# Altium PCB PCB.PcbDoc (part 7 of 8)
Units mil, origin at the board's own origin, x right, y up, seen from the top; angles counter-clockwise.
Board outline 11229.24 x 7764.43 mil, 14 copper layers (Top Layer, GND1, Signal 1, GND2, Signal 2, GND3, Singal 3, Power 1, GND4, Power 2, GND5, Power 3, GND6, Bottom Layer), stack 91.892 mil thick; 877 components, 305 nets, 2660 pads, 2851 vias.
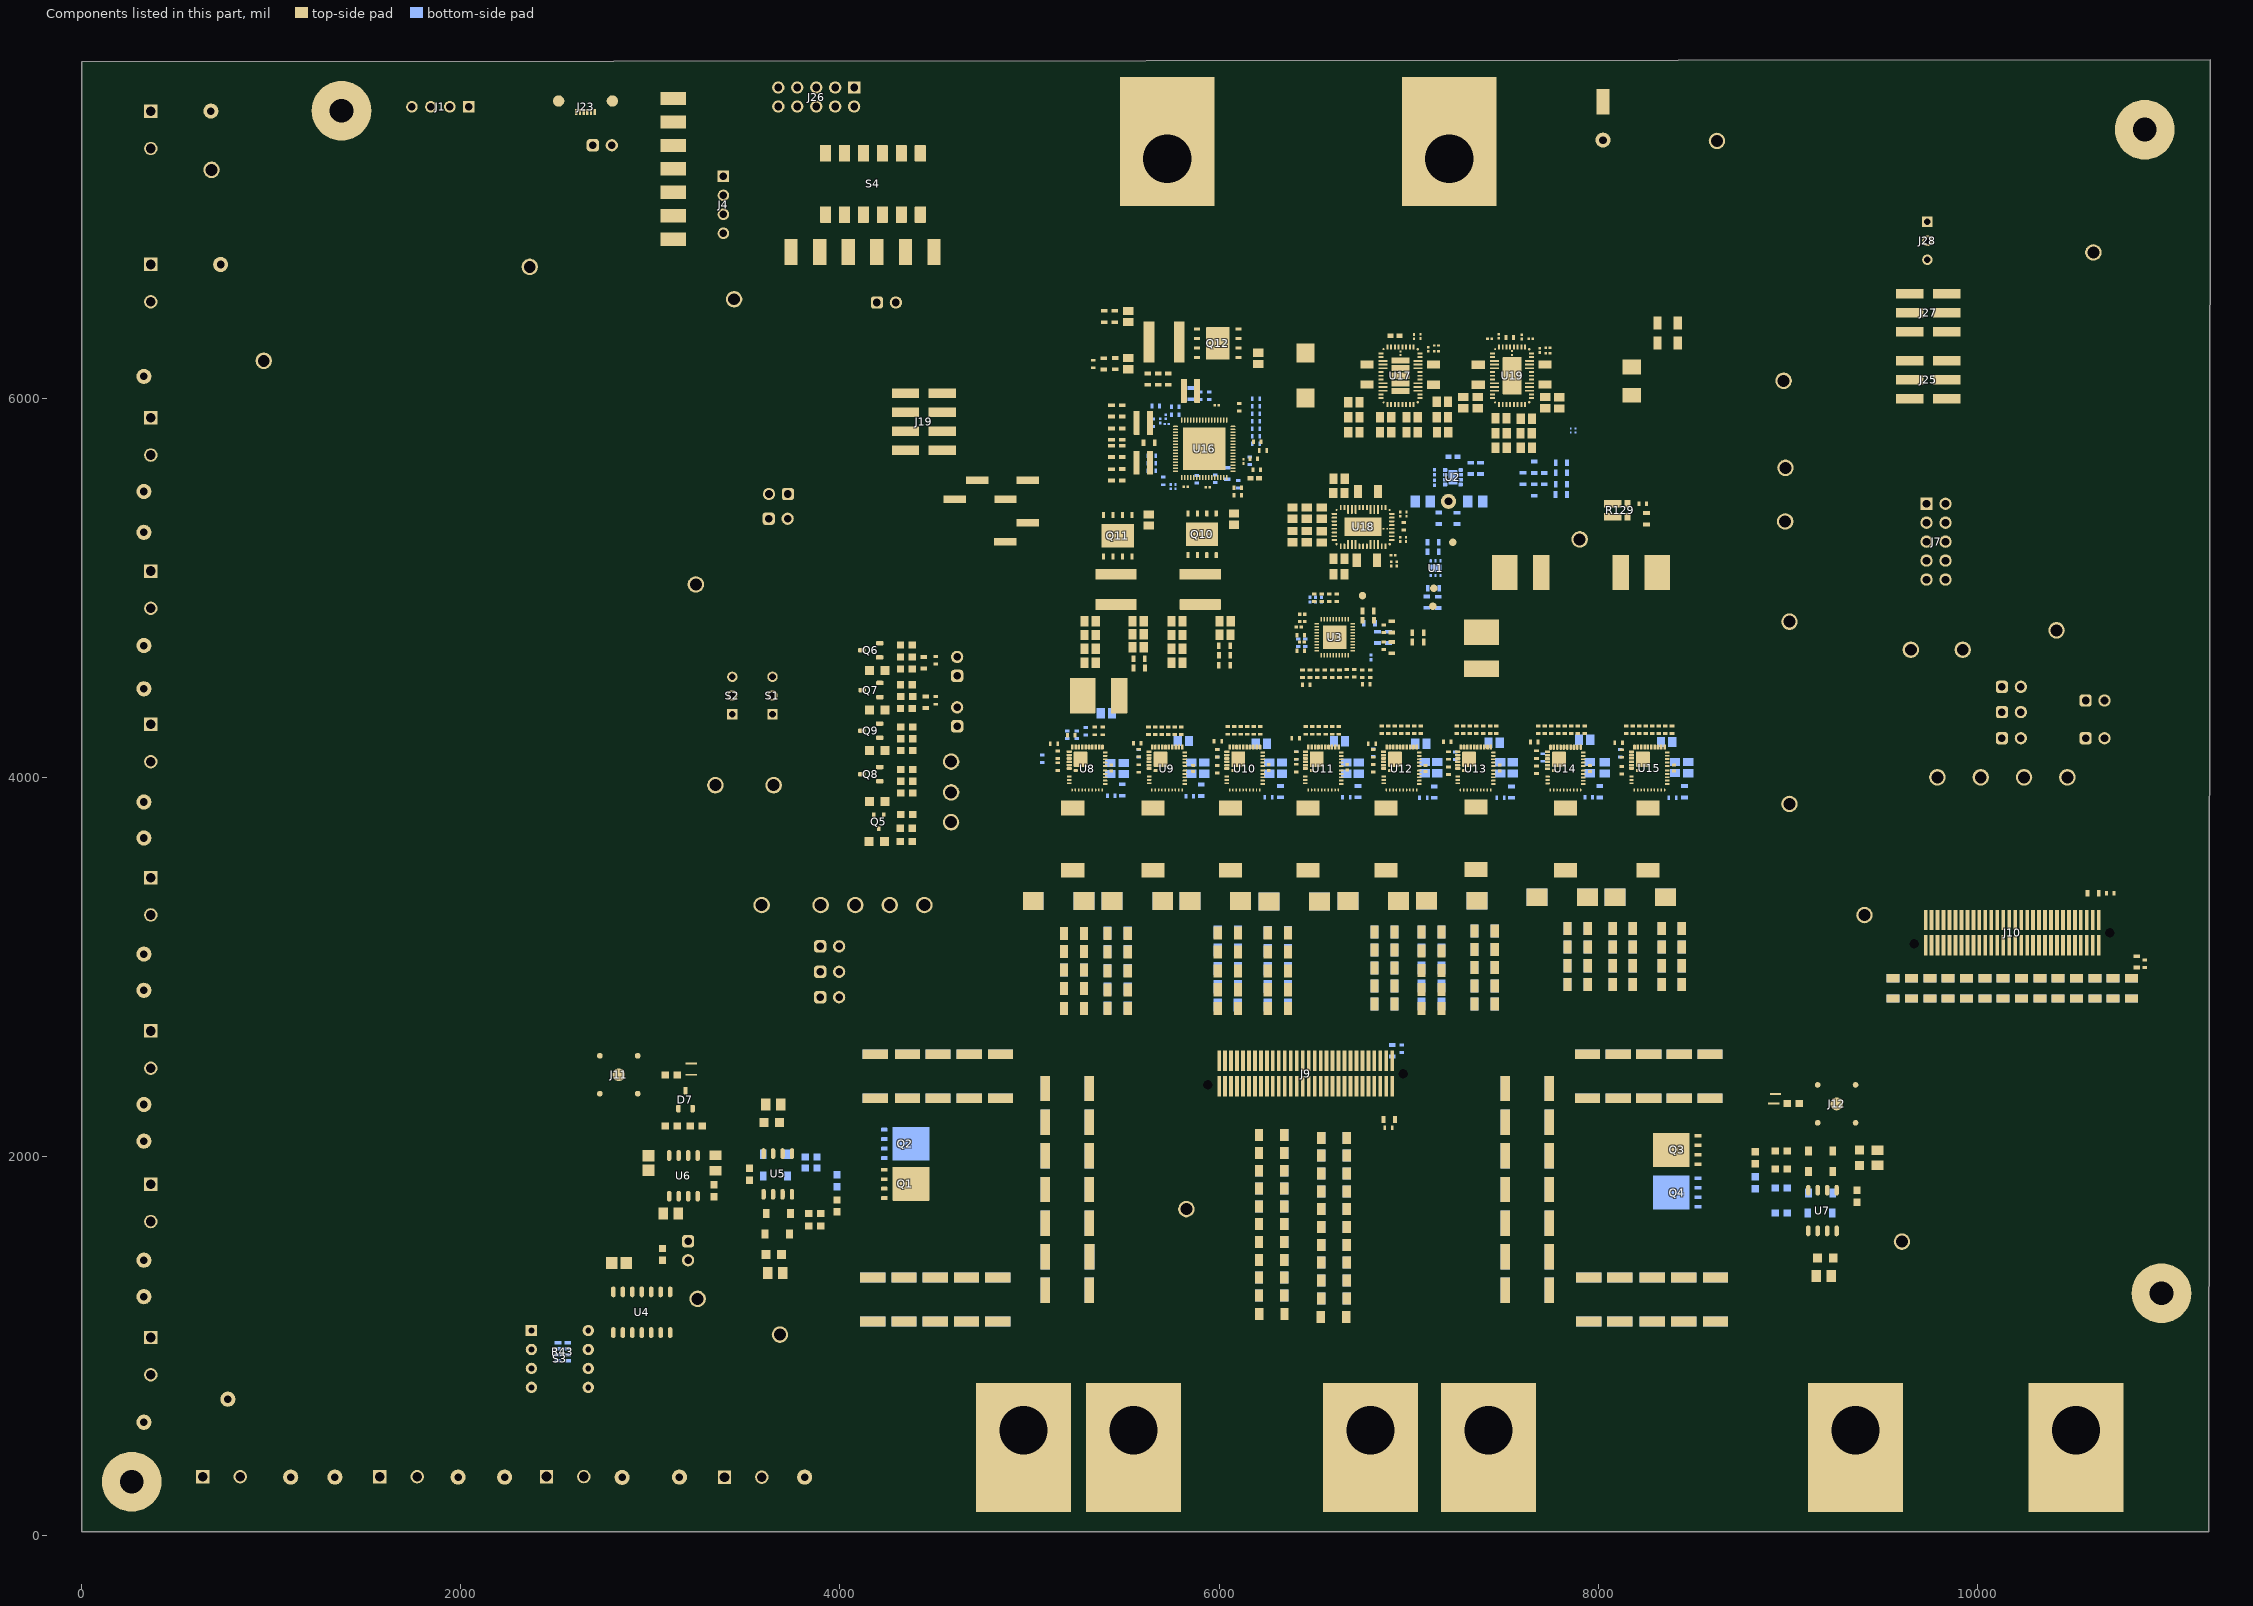
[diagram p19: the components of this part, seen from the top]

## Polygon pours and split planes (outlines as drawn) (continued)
GND on Top Layer "TOP_LAYER_GND_P228" (solid, pour order 228): 49.1,7702 70,7722.9 11155.9,7722.9 11174.4,7704.4 11168.51,7698.51 11168.51,107.92 11132.03,71.43 11131.56,71.9 93.47,71.43 49.1,115.8
NetC235_1 on Top Layer "TOP_LAYER_NETC235_1_P211" (solid, remove dead copper, pour order 211): 6807.22,3936.74 6807.22,3801.39 6814.15,3794.45 7033.7,3794.45 7058.6,3819.35 7058.6,3938.74 7050.65,3946.69 6817.16,3946.69
NetC219_1 on Top Layer "TOP_LAYER_NETC219_1_P210" (solid, remove dead copper, pour order 210): 6394.99,3935.22 6394.99,3802.13 6402.68,3794.45 6623.01,3794.45 6645.49,3816.94 6645.49,3938.97 6637.77,3946.69 6406.47,3946.69
NetC187_1 on Top Layer "TOP_LAYER_NETC187_1_P208" (solid, remove dead copper, pour order 208): 5577.22,3936.08 5577.22,3802.01 5585.13,3794.1 5804.01,3794.1 5821.44,3811.53 5821.44,3938.97 5813.71,3946.69 5587.83,3946.69
VINC on Top Layer "TOP_LAYER_VINC_P076" (solid, pour order 76): 137 vertices, not listed, extent 5316.29,4051.51 8511.42,5404.79
VTT on Top Layer "TOP_LAYER_VTT_P116" (solid, pour order 116): 6018.5,5591 6022.4,5594.9 6042.2,5594.9 6046.3,5590.8 6098.4,5538.7 6098.4,5453.31 6093.62,5448.53 6057.06,5448.53 6053,5452.59 6053,5533.3 6018.5,5567.8
VREF on Top Layer "TOP_LAYER_VREF_P231" (solid, pour order 231): 6802.4,4896.08 6806.85,4900.53 6858.37,4900.53 6881.85,4877.05 6881.85,4855.45 6876.6,4850.2 6808.23,4850.2 6802.4,4856.03
GND on Top Layer "TOP_LAYER_GND_P156" (solid, pour order 156): 9508.5,3112.9 9556.24,3160.63 10604.64,3160.63 10624.44,3140.83 10624.44,3022.13 10631.84,3014.73 10900.73,3014.73 10905.44,3010.02 10905.44,2911.95 10895.12,2901.63 9514.94,2901.63 9508.5,2908.07
PVOUT_B on Top Layer "TOP_LAYER_PVOUT_B_P153" (solid, pour order 153): 11070.28,3595.42 7686.78,3595.42 7606.48,3515.12 7606.48,2836.58 7763.18,2679.88 9197.62,2679.88 9908.91,1968.59 9908.91,77.59 9915.77,70.73 11123.43,70.73 11164.79,112.09 11164.79,3500.91
NetC267_1 on Top Layer "TOP_LAYER_NETC267_1_P094" (solid, remove dead copper, pour order 94): 7732.9,3937.63 7732.9,3811.11 7750.4,3793.6 7905.58,3793.6 7922.65,3810.67 7922.65,3938.11 7914.93,3945.84 7741.11,3945.84
BUCK6_OUT on Top Layer "TOP_LAYER_BUCK6_OUT_P213" (solid, pour order 213): 5786.29,4946.7 6022.99,4946.7 6029.09,4940.6 6029.09,4573.26 6022.22,4566.38 5786.61,4566.38 5780.49,4572.5 5780.49,4940.9
BUCK1_OUT on Top Layer "TOP_LAYER_BUCK1_OUT_P120" (solid, pour order 120): 5328.7,4946.7 5565.4,4946.7 5571.5,4940.6 5571.5,4558.67 5565.43,4552.6 5332.82,4552.6 5322.9,4562.52 5322.9,4940.9
NetC251_1 on Top Layer "TOP_LAYER_NETC251_1_P212" (solid, remove dead copper, pour order 212): 7256.4,3940.65 7256.4,3799.9 7261.85,3794.45 7446.23,3794.45 7453.4,3801.62 7453.4,3939.82 7446.53,3946.69 7262.44,3946.69
NetC203_1 on Top Layer "TOP_LAYER_NETC203_1_P209" (solid, remove dead copper, pour order 209): 5986.75,3935.88 5986.75,3801.47 5993.76,3794.45 6214.09,3794.45 6231.16,3811.53 6231.16,3938.97 6223.44,3946.69 5997.55,3946.69
NetC283_1 on Top Layer "TOP_LAYER_NETC283_1_P095" (solid, remove dead copper, pour order 95): 8175.92,3938.34 8175.92,3811.82 8193.43,3794.31 8348.6,3794.31 8365.67,3811.38 8365.67,3938.83 8357.95,3946.55 8184.13,3946.55
NetC171_1 on Top Layer "TOP_LAYER_NETC171_1_P011" (solid, remove dead copper, pour order 11): 5153.42,3935.4 5153.42,3802.55 5161.52,3794.45 5381.25,3794.45 5398.33,3811.53 5398.33,3938.97 5390.6,3946.69 5164.71,3946.69
VOUT_3 on Top Layer "TOP_LAYER_VOUT_3_P105" (solid, pour order 105): 21 vertices, not listed, extent 7548.67,5699.5 7840.57,6027.8
VOUT_1 on Top Layer "TOP_LAYER_VOUT_1_P202" (solid, pour order 202): 21 vertices, not listed, extent 6346.07,5025.8 6669.57,5317.7
VOUT_2 on Top Layer "TOP_LAYER_VOUT_2_P201" (solid, pour order 201): 21 vertices, not listed, extent 6346.07,5323.77 6669.57,5615.67
GND on Top Layer "TOP_LAYER_GND_P158" (solid, pour order 158): 7849.66,3422.79 7857.36,3430.49 8158.51,3430.49 8165.25,3423.74 8165.25,3296.64 8113.02,3244.42 8113.02,2862.1 8093.71,2842.79 7915.43,2842.79 7899.1,2859.12 7899.1,3251.6 7849.66,3301.04
5V_MODULE on Top Layer "TOP_LAYER_5V_MODULE_P103" (solid, pour order 103): 17 vertices, not listed, extent 6710.6,5677.3 7176.9,6027.8
NetQ1_5 on Top Layer "TOP_LAYER_NETQ1_5_P141" (solid, pour order 141): 4048.5,2479.92 4060.03,2491.46 5154.22,2491.46 5168.6,2477.08 5168.6,1204.52 5159.63,1195.56 4060.52,1195.56 4048.5,1207.58
GND on Top Layer "TOP_LAYER_GND_P143" (solid, pour order 143): 5204.7,3408.7 5212.4,3416.4 5504.4,3416.4 5509.2,3411.6 5509.2,3254.3 5468.06,3213.16 5468.06,2685.66 5458.5,2676.1 5243.7,2676.1 5236.1,2683.7 5236.1,3210.9 5204.7,3242.3
GND on Top Layer "TOP_LAYER_GND_P147" (solid, pour order 147): 6852.22,3403.64 6859.92,3411.34 7161.06,3411.34 7167.8,3404.6 7167.8,3260.33 7115.58,3208.1 7115.58,2751.63 7096.98,2733.04 6895.38,2733.04 6883.62,2744.81 6883.62,3205.84 6852.22,3237.24
NetQ3_5 on Top Layer "TOP_LAYER_NETQ3_5_P154" (solid, pour order 154): 8775.87,1207.09 8764.34,1195.56 7670.15,1195.56 7655.77,1209.93 7655.77,2482.49 7664.74,2491.46 8763.85,2491.46 8775.87,2479.43
PVOUT_A on Top Layer "TOP_LAYER_PVOUT_A_P167" (solid, pour order 167): 4043.8,2584.6 5043.1,3583.9 7495.66,3583.9 7562.77,3516.79 7562.77,2853.33 7756.1,2660 8774.2,2660 8778.8,2655.4 8778.8,76.18 8774.52,71.9 4048.35,71.9 4043.8,76.45
VIN on Top Layer "TOP_LAYER_VIN_P192" (solid, pour order 192): 50 vertices, not listed, extent 6073.6,6116.89 8353.5,7724.76
NetL1_2 on Top Layer "TOP_LAYER_NETL1_2_P099" (solid, pour order 99): 7882.72,6036.98 7917.73,6071.99 8517.11,6071.99 8539.5,6049.6 8539.5,5499.6 8516.14,5476.24 8135.84,5476.24 8133.26,5473.66 8133.26,5424.96 8124.1,5415.8 7890.87,5415.8 7882.72,5423.95
VIN on Top Layer "TOP_LAYER_VIN_P195" (solid, pour order 195): 6790.9,5249.3 6795,5253.4 6845.1,5253.4 6847.8,5250.7 6847.8,5201 6872.4,5176.4 6872.4,5109.8 6898.7,5083.5 6898.7,5022.8 6893.1,5017.2 6796.7,5017.2 6790.9,5023
VIN on Top Layer "TOP_LAYER_VIN_P193" (solid, pour order 193): 6789.7,5390.6 6794.3,5386 6843.1,5386 6848.2,5391.1 6848.2,5437.8 6871.3,5460.9 6871.3,5527.8 6897.6,5554.1 6897.6,5621.64 6891.74,5627.5 6766.84,5627.5 6759.86,5620.52 6759.86,5554.38 6789.89,5524.35
AGND2 on Top Layer "TOP_LAYER_AGND2_P186" (solid, pour order 186): 6879.68,5384.06 6913.05,5417.43 7007.57,5417.43 7021.62,5403.38 7021.62,5161.91 6952.08,5092.37 6898.59,5092.37 6879.68,5111.28
BUCK1_OUT on Top Layer "TOP_LAYER_BUCK1_OUT_P133" (solid, pour order 133): 4245.1,5851.29 4256.91,5863.1 4425.8,5863.1 4439.4,5849.5 4439.4,5363.8 5086,4717.2 5086,4589.46 5062.93,4566.38 4778.26,4566.38 4761.4,4583.25 4761.4,4634.1 4245.1,5150.4
PVIN345_V5ANA on Top Layer "TOP_LAYER_PVIN345_V5ANA_P125" (solid, pour order 125): 4455.9,5680.2 4455.9,6063.4 4476.1,6083.6 4738,6083.6 4760.8,6060.8 4760.8,5678.2 4744.84,5662.24 4473.86,5662.24
GND on Top Layer "TOP_LAYER_GND_P164" (solid, pour order 164): 7419.06,3231.51 7424.57,3237.01 7553.06,3237.01 7597.8,3192.27 7597.8,2768.1 7588.7,2759 7426.42,2759 7419.06,2765.84
GND on Top Layer "TOP_LAYER_GND_P159" (solid, pour order 159): 8406,3246.1 8411.5,3251.6 8540,3251.6 8549.78,3241.82 8549.78,2854.18 8538.38,2842.79 8415.57,2842.79 8406,2851.69
GND on Top Layer "TOP_LAYER_GND_P150" (solid, pour order 150): 17 vertices, not listed, extent 5981.3,1081.7 6897,2402.4
GND on Top Layer "TOP_LAYER_GND_P145" (solid, pour order 145): 6031.04,3408.71 6038.73,3416.4 6330.73,3416.4 6335.53,3411.6 6335.53,3254.3 6294.39,3213.16 6294.39,2756.69 6275.8,2738.1 6074.2,2738.1 6062.43,2749.87 6062.43,3210.9 6031.04,3242.3
PVINLDOA2_A3 on Top Layer "TOP_LAYER_PVINLDOA2_A3_P139" (solid, pour order 139): 4926.77,5373.75 4945.12,5392.1 5131.9,5392.1 5143.2,5380.8 5143.2,5313.8 5133.9,5304.5 4937.22,5304.5 4926.77,5314.95
BUCK6_OUT on Top Layer "TOP_LAYER_BUCK6_OUT_P137" (solid, pour order 137): 4534,5491.85 4548.75,5506.6 4930.9,5506.6 4953.1,5484.4 4953.1,5416.22 4915.69,5378.81 4915.69,5309.02 4953.1,5271.62 4953.1,5079.7 4929.8,5056.4 4808.9,5056.4 4786.9,5078.4 4786.9,5117.18 4545.58,5358.5 4534,5370.08
5V_MODULE on Top Layer "TOP_LAYER_5V_MODULE_P135" (solid, pour order 135): 4133.6,6073 4155.7,6095.1 4425.5,6095.1 4439.4,6081.2 4439.4,5887.25 4429.05,5876.9 4157.2,5876.9 4134,5900.1
VIN on Top Layer "TOP_LAYER_VIN_P129" (solid, pour order 129): 5923.63,5428.65 5937.28,5442.3 6216.24,5442.3 6225.03,5433.51 6225.03,5297.61 6217.53,5290.11 6131.53,5290.11 6121.93,5299.71 6121.93,5351.21 6106.83,5366.31 5926.43,5366.31 5923.63,5369.11
VIN on Top Layer "TOP_LAYER_VIN_P128" (solid, pour order 128): 5478.8,5431.2 5487.8,5440.2 5774.6,5440.2 5780.2,5434.6 5780.2,5290 5772.7,5282.5 5686.7,5282.5 5677.1,5292.1 5677.1,5343.6 5662,5358.7 5481.6,5358.7 5478.8,5361.5
BUCK2_OUT on Top Layer "TOP_LAYER_BUCK2_OUT_P126" (solid, pour order 126): 5665.66,6424.38 5665.66,6187.68 5659.56,6181.58 5218.76,6181.58 5200.56,6199.78 5200.56,6411.68 5219.06,6430.18 5659.86,6430.18
NetL12_1 on Top Layer "TOP_LAYER_NETL12_1_P123" (solid, pour order 123): 5898.25,6324.22 5900.75,6321.72 5900.75,6204.62 5881.75,6185.62 5760.95,6185.62 5756.85,6189.72 5756.85,6405.92 5763.95,6413.02 5815.15,6413.02 5821.25,6406.92 5821.25,6369.42 5866.45,6324.22
NetL11_1 on Top Layer "TOP_LAYER_NETL11_1_P119" (solid, pour order 119): 5430.3,5179 5432.8,5181.5 5549.9,5181.5 5568.9,5162.5 5568.9,5041.7 5564.8,5037.6 5348.6,5037.6 5341.5,5044.7 5341.5,5095.9 5347.6,5102 5385.1,5102 5430.3,5147.2
PVINLDOA2_A3 on Top Layer "TOP_LAYER_PVINLDOA2_A3_P117" (solid, pour order 117): 6058.5,5633.7 6060.8,5636 6087.8,5636 6121.5,5602.3 6178.84,5602.3 6182.47,5598.67 6182.47,5561.91 6177.46,5556.9 6126.3,5556.9 6105.6,5577.6 6105.6,5599.5 6079.6,5625.5 6060.8,5625.5 6058.5,5627.8
BUCK3_OUT on Top Layer "TOP_LAYER_BUCK3_OUT_P115" (solid, pour order 115): 5831.97,6101.13 5829.3,6103.8 5569.3,6103.8 5565.3,6099.8 5565.3,5974.6 5568.6,5971.3 5829.9,5971.3 5831.97,5973.37
BUCK4_OUT on Top Layer "TOP_LAYER_BUCK4_OUT_P114" (solid, pour order 114): 5578.34,5725.96 5582.4,5721.9 5582.4,5597 5578.5,5593.1 5316.3,5593.1 5310.7,5598.7 5310.7,5720.5 5316.16,5725.96
BUCK5_OUT on Top Layer "TOP_LAYER_BUCK5_OUT_P113" (solid, pour order 113): 5578.34,5936.16 5582.4,5932.1 5582.4,5807.2 5578.5,5803.3 5316.3,5803.3 5310.7,5808.9 5310.7,5930.7 5316.16,5936.16
LX4 on Top Layer "TOP_LAYER_LX4_P112" (solid, pour order 112): 5784.4,5721.99 5781.9,5719.49 5658.4,5719.49 5653.2,5714.29 5653.2,5595.89 5650.9,5593.59 5621.4,5593.59 5618.8,5596.19 5619.1,5596.49 5619.1,5721.19 5627.2,5729.29 5782.2,5729.29 5784.4,5727.09
PVIN345_V5ANA on Top Layer "TOP_LAYER_PVIN345_V5ANA_P110" (solid, pour order 110): 17 vertices, not listed, extent 5647,5735.6 5786.5,5793.2
LX5 on Top Layer "TOP_LAYER_LX5_P111" (solid, pour order 111): 5784.4,5805.9 5781.9,5808.4 5658.4,5808.4 5653.2,5813.6 5653.2,5932 5650.9,5934.3 5621.4,5934.3 5618.8,5931.7 5619.1,5931.4 5619.1,5806.7 5627.2,5798.6 5782.2,5798.6 5784.4,5800.8
LX3 on Top Layer "TOP_LAYER_LX3_P109" (solid, pour order 109): 5867,6100.2 5869.6,6102.8 5900.8,6102.8 5904.6,6099 5904.6,5873.2 5900.8,5869.4 5895.1,5869.4 5891.5,5873 5891.5,5940.9 5867,5965.4
AGND2_U19 on Top Layer "TOP_LAYER_AGND2_U19_P106" (solid, pour order 106): 20 vertices, not listed, extent 7450.7,6226.9 7763.6,6361.38
VOUT_4 on Top Layer "TOP_LAYER_VOUT_4_P104" (solid, pour order 104): 21 vertices, not listed, extent 7250.7,5704.3 7542.6,6027.8
GND on Top Layer "TOP_LAYER_GND_P102" (solid, pour order 102): 6880.1,5926.2 6885.6,5931.7 7010.4,5931.7 7015.7,5926.4 7015.7,5750.22 7012.08,5746.6 6883.6,5746.6 6880.1,5750.1
AGND1 on Top Layer "TOP_LAYER_AGND1_P100" (solid, pour order 100): 17 vertices, not listed, extent 6933.14,6232.4 7182.22,6403.19
VTT on Power 1 "POWER_1_VTT_P178" (solid, pour order 178): 31 vertices, not listed, extent 290.27,5448.31 6098.5,6780.1
GND on Power 1 "POWER_1_GND_P221" (solid, pour order 221): 49.1,7702 70,7722.9 11155.9,7722.9 11174.4,7704.4 11168.51,7698.51 11168.51,107.92 11132.03,71.43 11131.56,71.9 93.47,71.43 49.1,115.8
5V-AUX on Power 1 "POWER_1_5V-AUX_P098" (solid, pour order 98): 39 vertices, not listed, extent 2766.6,1488.77 7201.36,5319.65
BUCK6_OUT on Power 1 "POWER_1_BUCK6_OUT_P140" (solid, pour order 140): 6043,5546.3 6034,5555.3 6016.5,5555.3 6011.5,5550.3 6011.5,4800.27 5995.42,4784.19 5924,4784.19 5911.53,4771.73 5911.53,4699.27 5924.7,4686.1 5967.39,4686.1 6043,4761.8
LDOA1 on Power 1 "POWER_1_LDOA1_P175" (solid, pour order 175): 25 vertices, not listed, extent 1901.99,5939.24 5942.22,7574.3
LDOA3 on Power 1 "POWER_1_LDOA3_P174" (solid, pour order 174): 28 vertices, not listed, extent 2001.8,5577.6 6201.4,7575.1
5V-DRV on Power 1 "POWER_1_5V-DRV_P086" (solid, pour order 86): 17 vertices, not listed, extent 5050.5,4118.8 8315.68,5337.8
BUCK5_OUT on Power 1 "POWER_1_BUCK5_OUT_P181" (solid, pour order 181): 2968.6,5990.7 5397.6,5990.7 5408.4,5979.9 5408.4,5791 5396.4,5779 5004.2,5779 4838.2,5613 3968.5,5613 1151.4,2795.9 1151.4,104 1119.8,72.4 143.6,72.4 109.3,106.7 109.3,3131.4
VIN on Power 1 "POWER_1_VIN_P198" (solid, pour order 198): 6759.42,5622.76 6829.42,5692.76 7405.34,5692.76 7463.79,5634.31 7463.79,5555.29 7443.97,5535.47 7365.33,5535.47 7271.95,5628.85 6987.55,5628.85 6889.42,5530.73 6783.99,5530.73 6759.42,5555.3
VCCAUX on Power 1 "POWER_1_VCCAUX_P169" (solid, pour order 169): 23 vertices, not listed, extent 284.8,5869.05 5763.7,7567.9
BUCK4_OUT on Power 1 "POWER_1_BUCK4_OUT_P180" (solid, pour order 180): 4009,5571.6 4876.7,5571.6 5032.9,5727.8 5396,5727.8 5407.9,5715.9 5407.9,5480 4948.6,5020.7 4712.7,5020.7 2154,2462 2154,92.9 2133.9,72.8 1249.3,72.8 1221.5,100.6 1221.5,2784.1
PVIN345_V5ANA on Power 2 "POWER_2_PVIN345_V5ANA_P136" (solid, pour order 136): 19 vertices, not listed, extent 4612.1,5699.31 5899.49,6052.1
LDO3P3 on Power 2 "POWER_2_LDO3P3_P173" (solid, pour order 173): 24 vertices, not listed, extent 5650.75,5565.8 6142.8,5992.1
VREF on Power 2 "POWER_2_VREF_P085" (solid, pour order 85): 25 vertices, not listed, extent 5051.9,4162.59 8186.9,4878.2
5V_MODULE on Power 2 "POWER_2_5V_MODULE_P134" (solid, pour order 134): 29 vertices, not listed, extent 248.9,4930.8 7176.1,6134
GND on Power 2 "POWER_2_GND_P229" (solid, pour order 229): 49.1,7702 70,7722.9 11155.9,7722.9 11174.4,7704.4 11168.51,7698.51 11168.51,107.92 11132.03,71.43 11131.56,71.9 93.47,71.43 49.1,115.8
3.3V-Con on Power 2 "POWER_2_3.3V-CON_P084" (solid, pour order 84): 33 vertices, not listed, extent 2297.55,726.95 7183.9,4981.3
LDOA2 on Power 2 "POWER_2_LDOA2_P177" (solid, pour order 177): 25 vertices, not listed, extent 1793.36,5608.9 6193.6,7573.1
5V-AUX on Power 2 "POWER_2_5V-AUX_P096" (solid, pour order 96): 17 vertices, not listed, extent 7128.13,1823 9315.29,5410
PVINLDOA2_A3 on Power 2 "POWER_2_PVINLDOA2_A3_P138" (solid, pour order 138): 5085.4,5327.3 5085.4,5490.7 5146.74,5552.04 6074.04,5552.04 6125.76,5603.75 6156.49,5603.75 6166.65,5593.59 6166.65,5552.04 6105.31,5490.7 5168.4,5490.7 5143.9,5466.2 5143.9,5327.3 5128.9,5312.3 5100.4,5312.3
GND on Signal 1 "SIGNAL_1_GND_P216" (solid, pour order 216): 49.1,7702 70,7722.9 11155.9,7722.9 11174.4,7704.4 11168.51,7698.51 11168.51,107.92 11132.03,71.43 11131.56,71.9 93.47,71.43 49.1,115.8
SWA1 on Signal 1 "SIGNAL_1_SWA1_P176" (solid, pour order 176): 34 vertices, not listed, extent 1693.7,5560.42 5777.6,7573.9
GND on GND1 "GND1_GND_P215" (solid, pour order 215): 49.1,7702 70,7722.9 11155.9,7722.9 11174.4,7704.4 11168.51,7698.51 11168.51,107.92 11132.03,71.43 11131.56,71.9 93.47,71.43 49.1,115.8
VOUT_3 on Power 3 "POWER_3_VOUT_3_P191" (solid, pour order 191): 21 vertices, not listed, extent 93.9,4560.9 7874.5,6862.7
GND on Power 3 "POWER_3_GND_P225" (solid, pour order 225): 49.1,7702 70,7722.9 11155.9,7722.9 11174.4,7704.4 11168.51,7698.51 11168.51,107.92 11132.03,71.43 11131.56,71.9 93.47,71.43 49.1,115.8
PVIN345_V5ANA on Power 3 "POWER_3_PVIN345_V5ANA_P200" (solid, pour order 200): 6126.64,5747.65 6139.23,5735.07 6163.49,5735.07 6182.47,5754.05 6182.47,5904.84 6100.81,5986.5 5891.85,5986.5 5855.88,5950.53 5855.88,5924.64 5868.6,5911.92 5889.06,5911.92 5912.67,5935.53 6078.88,5935.53 6126.64,5887.76
LDO5V0 on Power 3 "POWER_3_LDO5V0_P199" (solid, pour order 199): 26 vertices, not listed, extent 5860.25,5513.8 6185.23,5931.5
VOUT_4 on Power 3 "POWER_3_VOUT_4_P190" (solid, pour order 190): 25 vertices, not listed, extent 109.8,3768.9 7449.8,6679.6
VOUT_1 on Power 3 "POWER_3_VOUT_1_P188" (solid, pour order 188): 17 vertices, not listed, extent 109.7,2171.6 6619.1,5221.73
VOUT_2 on Power 3 "POWER_3_VOUT_2_P189" (solid, pour order 189): 21 vertices, not listed, extent 109.7,2968 6557.97,5612.13
GND on GND2 "GND2_GND_P218" (solid, pour order 218): 49.1,7702 70,7722.9 11155.9,7722.9 11174.4,7704.4 11168.51,7698.51 11168.51,107.92 11132.03,71.43 11131.56,71.9 93.47,71.43 49.1,115.8
GND on Signal 2 "SIGNAL_2_GND_P217" (solid, pour order 217): 49.1,7702 70,7722.9 11155.9,7722.9 11174.4,7704.4 11168.51,7698.51 11168.51,107.92 11132.03,71.43 11131.56,71.9 93.47,71.43 49.1,115.8
GND on GND3 "GND3_GND_P219" (solid, pour order 219): 49.1,7702 70,7722.9 11155.9,7722.9 11174.4,7704.4 11168.51,7698.51 11168.51,107.92 11132.03,71.43 11131.56,71.9 93.47,71.43 49.1,115.8
GND on Singal 3 "SINGAL_3_GND_P220" (solid, pour order 220): 49.1,7702 70,7722.9 11155.9,7722.9 11174.4,7704.4 11168.51,7698.51 11168.51,107.92 11132.03,71.43 11131.56,71.9 93.47,71.43 49.1,115.8
GND on GND4 "GND4_GND_P222" (solid, pour order 222): 49.1,7702 70,7722.9 11155.9,7722.9 11174.4,7704.4 11168.51,7698.51 11168.51,107.92 11132.03,71.43 11131.56,71.9 93.47,71.43 49.1,115.8
GND on GND5 "GND5_GND_P224" (solid, pour order 224): 49.1,7702 70,7722.9 11155.9,7722.9 11174.4,7704.4 11168.51,7698.51 11168.51,107.92 11132.03,71.43 11131.56,71.9 93.47,71.43 49.1,115.8
GND on GND6 "GND6_GND_P226" (solid, pour order 226): 49.1,7702 70,7722.9 11155.9,7722.9 11174.4,7704.4 11168.51,7698.51 11168.51,107.92 11132.03,71.43 11131.56,71.9 93.47,71.43 49.1,115.8

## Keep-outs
Top Layer:
  region: 6085.2,5667.5 6100.6,5667.5 6103.9,5664.2 6136.2,5664.2 6138.3,5662.1 6138.3,5647.5 6136.5,5645.7 6101,5645.7 6092,5654.7 6085.2,5654.7
Bottom Layer:
  region: 3557.2,2042.9 3573.8,2059.5 3973.8,2059.5 4025.8,2007.5 4025.8,1812.6 4001.53,1788.33 3582.17,1788.33 3556.5,1814
Keep-Out Layer:
  text ".Layer_Name" at 577,-858.49 h60

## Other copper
Top Layer:
  pour cut-out: 8104.07,4135.24 8104.07,4157.16 8106.81,4159.9 8142.82,4159.9 8145.52,4157.2 8145.52,4142.59 8162.7,4125.41 8179.63,4125.41 8179.63,4107.5 8154.05,4107.5 8143.68,4117.88 8121.34,4117.88 8108.06,4131.16
  pour cut-out: 7654.67,4128.31 7654.67,4140.24 7664.61,4150.18 7687.36,4150.18 7695.05,4142.49 7695.05,4136.78 7706.74,4125.08 7729.15,4125.08 7729.15,4108.39 7696.88,4108.39 7680.18,4125.08 7657.84,4125.08 7657.58,4125.34
  pour cut-out: 7193.27,4120.69 7193.27,4149.44 7219.95,4149.44 7230.74,4138.65 7230.74,4132.13 7237.71,4125.16 7255.45,4125.16 7255.45,4108.58 7227.73,4108.58 7215.87,4120.43 7193.53,4120.43
  pour cut-out: 6793.62,4134.71 6793.62,4158.83 6795.28,4160.49 6831.29,4160.49 6833.99,4157.79 6833.99,4143.18 6851.17,4126 6868.1,4126 6868.1,4108.08 6842.52,4108.08 6819.12,4131.48 6796.78,4131.48 6796.52,4131.74
  pour cut-out: 6387.58,4123.78 6387.58,4147.89 6389.24,4149.55 6425.25,4149.55 6427.95,4146.85 6427.95,4132.24 6434.71,4125.48 6462.06,4125.48 6462.06,4107.43 6426.21,4107.43 6413.09,4120.55 6390.74,4120.55 6390.49,4120.81
  pour cut-out: 5970.48,4134.97 5970.48,4159.09 5972.14,4160.75 6008.15,4160.75 6010.85,4158.04 6010.85,4143.43 6028.03,4126.25 6044.96,4126.25 6044.96,4108.34 6019.38,4108.34 5995.98,4131.74 5973.64,4131.74 5973.38,4132
  pour cut-out: 5561.09,4134.04 5561.09,4158.16 5562.75,4159.82 5598.76,4159.82 5601.46,4157.12 5601.46,4142.51 5612.72,4131.25 5635.57,4131.25 5635.57,4113.48 5603.93,4113.48 5586.59,4130.81 5564.25,4130.81 5564,4131.07
  pour cut-out: 5128.2,4127.98 5128.2,4152.09 5129.86,4153.76 5165.87,4153.76 5168.57,4151.05 5168.57,4136.44 5179.83,4125.19 5202.68,4125.19 5202.68,4107.42 5171.03,4107.42 5153.7,4124.75 5131.36,4124.75 5131.1,4125.01
  pour cut-out: 9429.76,2347.4 9429.76,2208.6 9056.49,2208.6 9056.49,2347.4
  pour cut-out: 9056.43,2239.6 9056.43,2347.54 8893.82,2347.54 8893.82,2239.6
  pour cut-out: 3230.02,2392.3 3230.02,2500.24 3076.48,2500.24 3076.48,2392.3
  pour cut-out: 2670.24,2364.69 2670.24,2500.24 3076.48,2500.24 3076.48,2364.69
  text ".Layer_Name" at 577,-858.49 h60
Bottom Layer:
  text ".Layer_Name" at 577,-858.49 h60
Multi-Layer:
  pour cut-out: 10807.23,1214.25 ccw(c10969.96,1278.67) 11142.86,1251.55 ccw(c10969.96,1278.68)
  pour cut-out: 5557.35,6460.39 ccw(c5580.93,6460.39) 5580.93,6436.81 ccw(c5580.93,6460.39) 5604.51,6460.39 ccw(c5580.93,6460.39) 5580.93,6483.97 ccw(c5580.93,6460.39)
  pour cut-out: 8873.83,2304.29 ccw(c8873.83,2327.87) 8897.41,2327.87 ccw(c8873.83,2327.87) 8873.83,2351.45 ccw(c8873.83,2327.87) 8850.25,2327.87 ccw(c8873.83,2327.87)
  pour cut-out: 8184.39,2817.7 ccw(c8184.39,2841.28) 8207.97,2841.28 ccw(c8184.39,2841.28) 8184.39,2864.86 ccw(c8184.39,2841.28) 8160.81,2841.28 ccw(c8184.39,2841.28)
  pour cut-out: 8077.25,2819.21 ccw(c8077.25,2842.79) 8100.83,2842.79 ccw(c8077.25,2842.79) 8077.25,2866.37 ccw(c8077.25,2842.79) 8053.67,2842.79 ccw(c8077.25,2842.79)
  pour cut-out: 8873.83,2254.99 ccw(c8873.83,2278.57) 8897.41,2278.57 ccw(c8873.83,2278.57) 8873.83,2302.15 ccw(c8873.83,2278.57) 8850.25,2278.57 ccw(c8873.83,2278.57)
  pour cut-out: 6902.88,2746.04 ccw(c6926.45,2746.04) 6926.45,2722.46 ccw(c6926.45,2746.04) 6950.03,2746.04 ccw(c6926.45,2746.04) 6926.45,2769.62 ccw(c6926.45,2746.04)
  pour cut-out: 6796.58,2746.04 ccw(c6820.15,2746.04) 6820.15,2722.46 ccw(c6820.15,2746.04) 6843.73,2746.04 ccw(c6820.15,2746.04) 6820.15,2769.62 ccw(c6820.15,2746.04)
  pour cut-out: 3249.6,2489.38 ccw(c3273.18,2489.38) 3273.18,2465.8 ccw(c3273.18,2489.38) 3296.75,2489.38 ccw(c3273.18,2489.38) 3273.18,2512.96 ccw(c3273.18,2489.38)
  pour cut-out: 3248.3,2429.64 ccw(c3271.88,2429.64) 3271.88,2406.07 ccw(c3271.88,2429.64) 3295.45,2429.64 ccw(c3271.88,2429.64) 3271.88,2453.22 ccw(c3271.88,2429.64)

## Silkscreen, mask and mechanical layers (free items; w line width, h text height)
Top Overlay:
  lines w8: 7106.28,2522.7 7193.7,2522.7 7211.52,2540.52 7211.52,3217.6 7197.62,3231.51 7161.06,3231.51 ; 7108.1,2709.2 7210.6,2709.2 ; 7311.15,2709.2 7426.42,2709.2
  lines w10: 4293.12,5876.9 4262.08,5876.9 4229.3,5909.68 4229.3,6065.99 4242.11,6078.8 4274.3,6078.8 4300.76,6078.8 ; 4295.1,5676.1 4259.01,5676.1 4229.3,5705.81 4229.3,5832.43 4259.97,5863.1 4295.1,5863.1 ; 4960.8,5191.5 4950.12,5180.81 4950.7,3431.74 4950.7,2734.7 7209.2,2734.7 ; 4960.8,5616.3 4962.6,6494.6 8472.5,6494.6 ; 5548,-48 5566,-66 ; 6156.84,5648.7 6358.89,5648.7 6377.69,5667.5 6486.5,5667.5 ; 6225.03,5025.8 6551.87,5025.8 6565.07,5039 6565.07,5181.22 6573.18,5189.33 6581.51,5189.33 ; 6233.1,4906.27 6233.1,4991.09 6249,5006.98 6633.61,5006.98 6649.51,4991.09 6649.51,4966.58 ; 6233.1,5114.33 6324.06,5114.33 6331.3,5107.09 6331.3,5025.8 ; 6385.74,4906.31 6385.74,5006.98 ; 6468.21,4966.58 6468.21,5006.98 ; 7084.54,5560.9 7157.97,5560.9 7181.38,5584.31 7181.38,5705.32 7243.7,5767.64 7243.7,6017.45 7237.11,6024.04 7186.62,6024.04 ; 7310.08,2724.26 7793.29,2724.26 ; 7370.84,3234.21 7321.05,3234.21 7310.08,3223.24 7310.08,2543.72 7331.1,2522.7 7426.42,2522.7 ; 7796.95,2838.93 7911.6,2838.96 ; 7853.53,3248.85 7796.95,3248.85 7796.95,2744.73 7796.95,2711.1 7822.26,2685.8 7911.6,2685.8 ; 7911.6,2726.05 8075.82,2725.93 ; 8186.73,2724.26 8310.8,2724.26 ; 8414.03,2724.26 8479.19,2724.26 8479.19,2839.73 ; 31.4,39.45 3938.3,39.45 3938.3,591.3 3917.5,612.1 889.8,612.1 889.8,2160.2 888.3,2161.7 31.4,2161.7 31.4,39.45 ; 32.2,2178.7 889.3,2178.7 889.3,3751.1 32.2,3751.1 32.2,2178.7 ; 32.2,3796.1 889.3,3796.1 889.3,5368.5 32.2,5368.5 32.2,3796.1 ; 3134.4,2732.69 4745.2,2732.69 4745.2,4828.1 3134.4,4828.1 3134.4,2732.69 ; 3518.81,2765.11 4411.57,2765.11 4411.57,3180.27 3518.81,3180.27 3518.81,2765.11 ; 3726.6,3203.37 4619.37,3203.37 4619.37,3583.9 3726.6,3583.9 3726.6,3203.37 ; 9355.5,3784.27 10119.5,3784.27 10119.5,4102 9355.5,4102 9355.5,3784.27 ; 9357.6,4116.8 10314.3,4116.8 10314.3,4552.9 9357.6,4552.9 9357.6,4116.8 ; 9465.2,4798.2 10096.2,4798.2 10096.2,5800.7 9465.2,5800.7 9465.2,4798.2 ; 10133.9,3784.27 10897.9,3784.27 10897.9,4102 10133.9,4102 10133.9,3784.27 ; 10473.6,4115.2 11132.7,4115.2 11132.7,4613.3 10473.6,4613.3 10473.6,4115.2
  text "VCCAUX" at 68.7,7584.4 h60 r270
  text "SCL" at 3240.8,7558.7 h60
  text "VIN" at 8118.3,7530.5 h60
  text "TPS650861 / Programmer" at 4314,7503.5 h60
  text "VCCAUX" at 784.9,7486.2 h60
  text "TPS650861 / Ribbon Programmer" at 2238.9,7475.9 h60 r270
  text "SWA1" at 1693.95,7435.06 h60 r270
  text "LDOA2" at 1807.55,7435.06 h60 r270
  text "LDOA1" at 1921.15,7435.06 h60 r270
  text "LDOA3" at 2034.75,7435.06 h60 r270
  text "SDA" at 3236.2,7422.38 h60
  text "IRQB" at 3255.2,7301.8 h60
  text "GND" at 8541.2,7191.6 h60
  text "GND" at 818.84,7174.45 h60
  text "GPO1" at 2792.23,7166.6 h60
  text "GPO1" at 3479.5,7148.6 h60
  text "GPO2" at 2772.24,7050.63 h60
  text "GPO2" at 3479.5,7042.63 h60
  text "GPO3" at 3479.5,6938.6 h60
  text "GPO3" at 2772.24,6927.7 h60
  text "EN" at 9510.93,6898.8 h60
  text "GPO4" at 3479.5,6841.17 h60
  text "GPO4" at 2772.24,6802.8 h60
  text "U17_EN" at 9281,6796.9 h60
  text "OFF" at 9450.94,6699.1 h60
  text "VTT" at 68.7,6678.8 h60 r270
  text "VTT" at 852.8,6672.1 h60
  text "CTL1" at 3710.2,6635.5 h60 r270
  text "CTL2" at 3861.12,6635.5 h60 r270
  text "CTL3" at 4012.04,6635.48 h60 r270
  text "CTL5" at 4370.4,6635.48 h60 r270
  text "CTL6" at 4476,6635.48 h60 r270
  text "GND" at 10511.95,6575.78 h60
  text "EN" at 9384.31,6529.6 h60
  text "EN" at 10009.4,6527.1 h60
  text "GND" at 2275.64,6504.65 h60
  text "U19_EN1" at 9114.4,6434.45 h60
  text "U19_EN2" at 10009.4,6422.25 h60
  text "CTL4" at 4132.8,6369.2 h60
  text "GND" at 3359.34,6351.95 h60
  text "OFF" at 9324.33,6329.9 h60
  text "OFF" at 10009.4,6327.4 h60
  text "EN" at 9384.31,6175.9 h60
  text "EN" at 10008.3,6173.4 h60
  text "GND" at 1112.3,6160.4 h60
  text "U18_EN1" at 9114.4,6071.5 h60
  text "U18_EN2" at 10008.6,6071.5 h60
  text "5V_MODULE" at 68.7,6060 h60 r270
  text "OFF" at 9324.33,5976.2 h60
  text "OFF" at 10008.3,5973.7 h60
  text "5V_MODULE" at 3686.5,5967.4 h60
  text "GND" at 8886.1,5920.6 h60
  text "BUCK1_OUT" at 3696.5,5743.69 h60
  text "TPS53688 PMBUS" at 9504.19,5718.98 h72.83
  text "PVIN345_ / V5ANA" at 4854.2,5688.9 h60 r90
  text "PVINSWB1_B2" at 4606.25,5632.82 h40
  text "PVINSWA1" at 5011.2,5613.93 h40
  text "VOUT_B SENSE" at 3347.9,5590.5 h60
  text "BUCK6_OUT" at 4290.6,5451.3 h40
  text "5V_INT" at 7299.21,5450.97 h60
  text "TPS53688" at 2970.5,5405.6 h60
  text "BUCK6_OUT" at 4634.99,5365.6 h40
  text "VINC" at 7671.03,5350.2 h60
  text "U19 Module Output" at 782.29,5318.5 h60 r270
  text "PVINLODA2_A3" at 5009.6,5275.96 h40
  text "BUCK6_OUT" at 4565.8,5228.83 h40
  text "VOUT_A SENSE" at 3347.9,5220.3 h60
  text "5V-DRV" at 7124.1,5168.35 h60
  text "VOUT_3" at 68.7,5163.1 h60 r270
  text "TPS53688 Current  / Sense Resistor" at 9209.28,5093.65 h72.83 r90
  text "3V3-LDO" at 7052.54,5032.12 h60
  text "GND" at 2938.84,4982.75 h60
  text "VREF" at 6779.6,4957.8 h60
  text "3V3-CON" at 7167.38,4890.31 h60
  text "GND" at 10338.5,4861.6 h60
  text "TPS53688 EN and Indication LEDs" at 3334.03,4858.78 h90
  text "ON" at 3491.4,4705.4 h60
  text "TSENB" at 9373.7,4655.87 h60
  text "TSENA" at 10019.3,4655.87 h60
  text "GND" at 8910.18,4636.15 h60
  text "1" at 3973.19,4566.2 h60
  text "BCSP" at 10507.9,4517.6 h60
  text "ACSP" at 9389.57,4459.05 h60
  text "EN_VOUT_B" at 4720.33,4455.9 h50 r90
  text "IOUT4" at 9697.3,4450.8 h60
  text "BIOUT2" at 10764.82,4380.05 h60
  text "VOUT_4" at 68.7,4340 h60 r270
  text "2" at 3953.2,4328.2 h60
  text "IOUT5" at 9697.3,4316.3 h60
  text "EN_VOUT_B" at 3294,4184.1 h60 r90
  text "EN_VOUT_A" at 3829.9,4184.1 h60 r90
  text "BIOUT1" at 10764.82,4174.55 h60
  text "IOUT6" at 9697.3,4173.5 h60
  text "EN_VOUT_A" at 4720.33,4170.34 h50 r90
  text "3" at 3953.2,4127.1 h60
  text "OFF" at 3464.8,4100.5 h60
  text "APWM" at 9383.5,4002.3 h60
  text "BPWM" at 10621.9,3976.9 h60
  text "4" at 3953.2,3851.7 h60
  text "5" at 9763.87,3819.6 h60
  text "6" at 9996.95,3819.6 h60
  text "2" at 10226.15,3819.6 h60
  text "1" at 10471.2,3819.6 h60
  text "EN_VOUT_B" at 3179.6,3818.36 h60
  text "EN_VOUT_A" at 3553.7,3818.36 h60
  text "U18 Module Output" at 787.09,3715.6 h60 r270
  text "GND" at 8929.18,3685.35 h60
  text "Phase A and B PWM and Iout Test Points" at 9408.06,3685.35 h72.83
  text "5" at 3953.2,3665.1 h60
  text "VOUT_2" at 67.4,3539.7 h60 r270
  text "APWM" at 3744.5,3503.1 h90
  text "1. EN_VOUT_B / 2. EN_VOUT_A / 3. VOUT_A_RDY / 4. VOUT_B_RDY / 5. VR_FAULT#" at 3255.8,3458.2 h60
  text "1" at 4442.18,3426.4 h60
  text "2" at 4245.51,3422.55 h60
  text "4" at 3865.7,3419 h60
  text "3" at 4068.4,3419 h60
  text "GND" at 3288.4,3283.1 h60
  text "PVOUT_B" at 8985.12,3095.24 h60
  text "IOUT3" at 4097.7,3078.3 h60
  text "ACSP" at 3545.2,3074.1 h60
  text "IOUT2" at 4097.7,2942.2 h60
  text "IOUT1" at 4097.7,2807.6 h60
  text "VOUT_1" at 69.9,2719.9 h60 r270
  text "C240_Out" at 2649.2,2678.7 h60
  text "C147_Out" at 9010.67,2511.45 h60
  text "TPS650861 Output" at 771.09,2104.8 h60 r270
  text "BUCK2_OUT" at 69.9,2007.1 h60 r270
  text "PVOUT_A" at 5584.3,1539.5 h60
  text "GND" at 9512.77,1369.87 h60
  text "BUCK3_OUT" at 68.5,1196.3 h60 r270
  text "PVOUT_B" at 10318.2,972.6 h60
  text "PVOUT_A" at 6930.1,965.5 h60
  text "GND" at 3598.4,883.2 h60
  text "BUCK5_OUT" at 532.2,57.78 h50
  text "BUCK4_OUT" at 1455.85,57.78 h50
  text "BUCK6_OUT" at 2331.67,57.78 h50
  text "BUCK1_OUT" at 3284.84,57.78 h50
  text ".Layer_Name" at 577,-858.49 h60
Bottom Overlay:
  text ".Layer_Name" at 577,-858.49 h60
Top Paste:
  text ".Layer_Name" at 577,-858.49 h60
Bottom Paste:
  text ".Layer_Name" at 577,-858.49 h60
Top Solder:
  text ".Layer_Name" at 577,-858.49 h60
  text ".Layer_Name" at 577,-858.49 h60
Bottom Solder:
  text ".Layer_Name" at 577,-858.49 h60
Drill Guide:
  text ".Layer_Name" at 577,-858.49 h60
M1 Board Outline:
  lines w10: 0,21 11220.99,21 11229.68,7785.03 0,7775.19 0,21
  text ".Layer_Name" at 577,-858.49 h60
M2 Board Dimensions:
  rectangle: 0,-275 125,-150
  rectangle: 125,-400 500,-275
  lines w7: 0,-275 1000,-275 ; 125,-400 125,-150 ; 250,-400 250,-150 ; 500,-400 500,-150 ; 750,-400 750,-150 ; 0,-400 1000,-400 1000,-150 0,-150 0,-400
  text ".Layer_Name" at 577,-858.49 h60
M3 3D STEP Top:
  text ".Layer_Name" at 577,-858.49 h60
M4 3D STEP Bottom:
  text ".Layer_Name" at 577,-858.49 h60
M5 Assembly Top:
  lines w10: -292,-930.17 6308,-930.17 ; -292,-726.83 6310,-726.83 ; -292,-523.5 -292,-1133.5 3713,-1133.5 6310,-1133.5 6310,-523.5 -291.5,-523.5 -291.5,-1133.5 1284,-1133.5 ; 2173,-1133.5 2173,-523.5 ; 3440,-726.83 3440,-523.5 ; 4280,-726.83 4280,-523.5 ; 4902,-1140 4902,-937.17
  text "COMPONENTS MARKED 'DNP' SHOULD NOT BE POPULATED." at 1153.5,-318.5 h60
  text "ASSEMBLY VARIANT:" at 1153,-434 h60
  text ".VariantName" at 2189,-434 h60
  text "PCB VIEWED FROM TOP SIDE" at -228.5,-655.67 h60
  text "BOARD #:" at 2248,-655.67 h60
  text ".PRJ_Number" at 2793.5,-655.67 h60
  text "REV:" at 3638,-655.67 h60
  text ".PCB_Rev" at 3929.5,-655.67 h60
  text "SVN REV:" at 4476,-655.67 h60
  text ".VersionControl_RevNumber" at 4982,-655.67 h60
  text "TID #:" at 2248,-859 h60
  text ".TID" at 2793.5,-859 h60
  text "PLOT NAME =" at -228.5,-1064.34 h60
  text ".plot_File_Name" at 577,-1064.34 h60
  text "GENERATED    :" at 2250,-1064.34 h60
  text ".Print_Date" at 3119.5,-1064.34 h60
  text ".Print_Time" at 3848.5,-1064.34 h60
  text "TEXAS INSTRUMENTS" at 5113,-1064.34 h60
M6 Assembly Bottom:
  lines w10: -292.5,-727.33 6309.5,-727.33 ; -290.5,-930.67 6309.5,-930.67 ; 1115.5,-1140.5 1115.5,-937.67 ; 1737.5,-727.33 1737.5,-524 ; 2577.5,-727.33 2577.5,-524 ; 3844.5,-1134 3844.5,-524 ; 4733.5,-1134 6309,-1134 6309,-524 -292.5,-524 -292.5,-1134 2304.5,-1134 6309.5,-1134 6309.5,-524
  text "COMPONENTS MARKED 'DNP' SHOULD NOT BE POPULATED." at 6102,-318 h60
  text ".VariantName" at 5058,-434 h60
  text "ASSEMBLY VARIANT:" at 6097,-434 h60
  text ".VersionControl_RevNumber" at 1035.5,-656.17 h60
  text "SVN REV:" at 1541.5,-656.17 h60
  text ".PCB_Rev" at 2088,-656.17 h60
  text "REV:" at 2379.5,-656.17 h60
  text ".PRJ_Number" at 3224,-656.17 h60
  text "BOARD #:" at 3769.5,-656.17 h60
  text "PCB VIEWED FROM BOTTOM SIDE" at 6246,-656.17 h60
  text ".TID" at 3224,-859.5 h60
  text "TID #:" at 3769.5,-859.5 h60
  text "TEXAS INSTRUMENTS" at 904.5,-1064.84 h60
  text ".Print_Time" at 2169,-1064.84 h60
  text ".Print_Date" at 2898,-1064.84 h60
  text "GENERATED    :" at 3767.5,-1064.84 h60
  text ".plot_File_Name" at 5440.5,-1064.84 h60
  text "PLOT NAME =" at 6246,-1064.84 h60
M9 Title Sheet:
  drawing of 57 lines, arcs and shapes, not listed
  text "1" at 739.84,8036.5 h70
  text "2" at 3235.5,8036.5 h70
  text "3" at 5724.84,8036.5 h70
  text "4" at 8231.51,8036.5 h70
  text "5" at 10730.5,8036.5 h70
  text "6" at 13235.5,8036.5 h70
  text "A" at -416.5,6893.5 h70
  text "A" at 14383.5,6893.5 h70
  text "B" at -416.5,4513.5 h70
  text "B" at 14383.5,4513.5 h70
  text "C" at -416.5,2138.5 h70
  text "C" at 14383.5,2138.5 h70
  text "PROJECT TITLE:" at 11343.5,277.5 h45
  text ".PRJ_Title" at 11393.5,144.17 h70
  text "DESIGNED FOR:" at 11343.5,-23.5 h45
  text ".PRJ_Customer" at 11393.5,-163.5 h70
  text "D" at -416.5,-231.5 h70
  text "D" at 14383.5,-231.5 h70
  text "FILE NAME:" at 11343.5,-323.5 h45
  text ".PCB_File_Name_No_Path" at 11393.5,-443.5 h70
  text "Texas Instruments (TI) and/or its licensors do not warrant the accuracy or completeness of this specification" at 6374,-605.34 h45
  text "ENGINEER:" at 11343.5,-613.5 h45
  text "LAYOUT BY:" at 12848.5,-613.5 h45
  text "or any information contained therein. TI and/or its licensors do not warrant that this design will meet" at 6329.01,-718 h45
  text ".PRJ_Engineer" at 11393.5,-768.49 h70
  text ".PCB_Layout" at 12899,-768.49 h70
  text "the specifications, will be suitable for your application or fit for any particular purpose, or will operate in" at 6329.01,-830.67 h45
  text ".Layer_Name" at 577,-858.49 h60
  text "ALTIUM DESIGNER VERSION:" at 12848.5,-923.5 h45
  text "an implementation. TI and/or its licensors do not warrant that the design is production worthy. You should" at 6329.01,-943.33 h45
  text "completely validate and test your design implementation to confirm the system functionality for your application." at 6374,-1056 h45
  text ".print_Scale" at 11393.5,-1056.83 h70
  text ".Application_BuildNumber" at 12899,-1056.83 h70
  text "1" at 739.84,-1263.5 h70
  text "2" at 3235.5,-1263.5 h70
  text "3" at 5724.84,-1263.5 h70
  text "4" at 8231.51,-1263.5 h70
  text "5" at 10730.5,-1263.5 h70
  text "6" at 13235.5,-1263.5 h70
M10 Fab Notes:
  drawing of 189 lines, arcs and shapes, not listed
  text "DESIGN INFORMATION" at 12382.02,6356.17 h60
  text "MIN. TRACK WIDTH:" at 11737.46,6224.05 h60
  text "8" at 12833.7,6224.05 h60
  text "MIL" at 12988.46,6224.05 h60
  text "MIN. CLEARANCE:" at 11737.46,6099.92 h60
  text "7.874" at 12667.32,6099.92 h60
  text "MIL" at 12988.46,6099.92 h60
  text "MIN. VIA PAD SIZE:" at 11737.46,5975.8 h60
  text "24" at 12803.71,5975.8 h60
  text "MIL" at 12988.46,5975.8 h60
  text "0.05mm (2MIL)" at 12432.46,5845.9 h60
  text "MINIMUM ANNULAR RING" at 11408.23,5837.67 h60
  text "EXTERNAL" at 13140.46,5837.67 h60
  text "PER" at 11608.23,5727.55 h60
  text "IPC-D-275 CLASS 2 LEVEL C" at 11828.23,5727.54 h60
  text "MIL, HOLES" at 13316.46,5627.07 h60
  text "+/-" at 12924,5618.48 h60
  text "+/-" at 13778,5618.48 h60
  text "REGISTRATION TOLERANCES:" at 11408.23,5617.42 h60
  text "METAL" at 12608,5617.42 h60
  text "5" at 13184.2,5617.42 h60
  text "3" at 14017.2,5617.42 h60
  text "MIL" at 14133.46,5617.42 h60
  text "HOLE SIZE TOLERANCE (UNLESS OTHERWISE SPECIFIED):" at 11408.23,5519.1 h60
  text "+/-" at 13778,5516.23 h60
  text "3" at 14017.2,5515.17 h60
  text "MIL" at 14133.46,5515.17 h60
  text "MATERIAL:" at 11333.46,5377.52 h60
  text "FR-4 High Tg" at 12319.9,5249 h60
  text "X" at 12175.46,5241.01 h60
  text "FR-408" at 11754.46,5236.49 h60
  text "OTHER" at 13242.46,5236.49 h60
  text "X" at 13241.12,5103.9 h60
  text "62 MIL (1.6mm) +/-10%" at 12074.56,5093.46 h60
  text "96 MIL (2.4mm) +/-10%" at 13667.36,5088.46 h60
  text "THICKNESS:" at 11408.23,5085.24 h60
  text "OTHER" at 13359.46,5085.24 h60
  text "TOLERANCE:" at 11408.23,4946.92 h60
  text "X" at 12256.46,4946.92 h60
  text "ANSI IPC-6012 TYPE 3 CLASS 2" at 12434.48,4946.92 h60
  text "OTHER +/-" at 12434.46,4802.73 h60
  text "BOW & TWIST:" at 11408.23,4657.54 h60
  text "X" at 12256.46,4657.54 h60
  text "ANSI IPC-6012 TYPE 3 CLASS 2" at 12434.48,4657.54 h60
  text "OTHER +/-" at 12434.46,4510.85 h60
  text "DRILLING:" at 11333.46,4380.23 h60
  text "NC_DRILL FILES" at 13094.46,4275.04 h60
  text "REFERENCE:" at 11408.23,4271.1 h60
  text "X" at 12065.46,4271.01 h60
  text "AS SHOWN" at 12243.46,4271.1 h60
  text "X" at 12966.46,4271.1 h60
  text "OTHER" at 13392.46,4128.85 h60
  text "PTH COPPER THICKNESS:" at 11407.91,4125.32 h60
  text "X" at 12547.14,4125.32 h60
  text "20-30 um" at 12675.14,4125.32 h60
  text "BOARD FINISH:" at 11333.46,3977.73 h60
  text "SILKSCREEN:" at 11488.68,3867.6 h60
  text "X" at 12446.46,3867.6 h60
  text "TOP" at 12563.46,3867.6 h60
  text "X" at 12956.46,3867.6 h60
  text "BOTTOM" at 13074.46,3867.6 h60
  text "SILKSCREEN COLOR:" at 11488.68,3712.41 h60
  text "X" at 12445.46,3712.41 h60
  text "WHITE" at 12563.46,3712.41 h60
  text "OTHER" at 13074.46,3712.41 h60
  text "X" at 12576.46,3568.96 h60
  text "GREEN" at 12694.46,3568.96 h60
  text "OTHER" at 13312.46,3568.96 h60
  text "SOLDER RESIST COLOR:" at 11488.68,3562.1 h60
  text "X" at 12576.46,3414.71 h60
  text "MATTE" at 12694.46,3414.71 h60
  text "SEMI-GLOSS" at 13312,3414.07 h60
  text "IMMERSION GOLD (ENIG)" at 12394.46,3241.94 h60
  text "ENEPIG" at 13732,3234.72 h60
  text "SURFACE FINISH:" at 11333.46,3233.72 h60
  text "X" at 12216.46,3233.72 h60
  text "IMM. TIN/SILVER OR EQUIV" at 11663,3096.4 h60
  text "OTHER" at 13094.46,3092.47 h60
  text "ARRAY/PANEL:" at 11333.46,2937.09 h60
  text "CUT AND TRIM PER M1 BOARD OUTLINE" at 12394.46,2928.87 h60
  text "N.C. ROUTE" at 12394.46,2792.9 h60
  text "X" at 13082.46,2792.9 h60
  text "V. SCORE" at 13260.46,2792.9 h60
  text "CERTIFICATION:" at 11333.46,2663.77 h60
  text "MATERIALS AND WORKMANSHIP FOR ALL PCBS" at 12058.46,2663.77 h60
  text "TO MEET OR EXCEED THE REQUIREMENTS OF:" at 12058.46,2569.71 h60
  text "X" at 11695.97,2441.08 h60
  text "ANSI IPC-A-600F CLASS ->" at 11823.96,2441.08 h60
  text "X" at 13471.97,2441.08 h60
  text "2" at 13581.96,2441.08 h60
  text "3" at 13935.96,2439.58 h60
  text "1" at 13386.71,2431.1 h60
  text "X" at 12507.97,2293.39 h60
  text "RoHS" at 12635.96,2293.39 h60
  text "OTHER" at 13280.36,2293.39 h60
  text "PER ORDER" at 13677.42,2293.39 h60
  text "ALL BOARDS MUST MEET OR EXCEED UL94-V0 REQUIREMENTS." at 11361,2139.57 h60
  text "PCB MUST BEAR THE UL94V-0 UL REGISTERED MATERIAL ID NUMBER" at 11361,2023.5 h60
  text "ADDITIONAL REQUIREMENTS:" at 11333.46,1854.08 h60
  text "MICROSECTION:" at 11408.23,1746.95 h60
  text "YES" at 12313.96,1746.95 h60
  text "REQUIRED" at 13175.46,1602.62 h60
  text "BARE BOARD ELEC. TEST:" at 11408.23,1599.76 h60
  text "NONE" at 12713.96,1599.76 h60
  text "X" at 13057.46,1599.76 h60
  text "PER ORDER" at 13767.46,1599.76 h60
  text "XX MIL VIAS REQUIRE NON-CONDUCTIVE FILL AND PLANARIZE" at 11576.38,1394.82 h59
  text "XX MIL VIAS REQUIRE CONDUCTIVE FILL AND PLANARIZE" at 11584.38,1290.84 h60
  text "OUTER XX MIL TRACES REQUIRE 50 OHM SINGLE-ENDED IMPEDANCE" at 11583.39,1127.46 h58
  text "LAYER 2 & 3 (INNER LAYERS) XX MIL WIDE, XX MIL SPACE / TRACES REQUIRE 100 OHM DIFFERENTIAL IMPEDANCE" at 11575.39,891.74 h60
  text ".Layer_Name" at 577,-858.49 h60
M11 Gerber Information:
  lines w10: -292,-930.17 6308,-930.17 ; -292,-726.83 6310,-726.83 ; -292,-523.5 -292,-1133.5 3713,-1133.5 6310,-1133.5 6310,-523.5 -291.5,-523.5 -291.5,-1133.5 1284,-1133.5 ; 2173,-1133.5 2173,-523.5 ; 3440,-726.83 3440,-523.5 ; 4280,-726.83 4280,-523.5 ; 4902,-1140 4902,-937.17
  text "ALL ARTWORK VIEWED FROM TOP SIDE" at -228.5,-655.67 h60
  text "BOARD #:" at 2248,-655.67 h60
  text ".PRJ_Number" at 2793.5,-655.67 h60
  text "REV:" at 3638,-655.67 h60
  text ".PCB_Rev" at 3929.5,-655.67 h60
  text "SVN REV:" at 4476,-655.67 h60
  text ".VersionControl_RevNumber" at 4982,-655.67 h60
  text "LAYER NAME =" at -228.5,-858.49 h60
  text "TID #:" at 2248,-859 h60
  text ".TID" at 2793.5,-859 h60
  text "PLOT NAME =" at -228.5,-1064.34 h60
  text ".plot_File_Name" at 577,-1064.34 h60
  text "GENERATED    :" at 2250,-1064.34 h60
  text ".Print_Date" at 3119.5,-1064.34 h60
  text ".Print_Time" at 3848.5,-1064.34 h60
  text "TEXAS INSTRUMENTS" at 5113,-1064.34 h60
M12 Stackup:
  drawing of 536 lines, arcs and shapes, not listed
  text "Layer" at -1521.74,11546 h60
  text "Name" at -1270.65,11546 h60
  text "Material" at -785.07,11546 h60
  text "Thickness" at -348.72,11546 h60
  text "Constant" at 9.71,11546 h60
  text "Board Layer Stack" at 341.44,11546 h60
  text "Top Overlay" at -1270.65,11426 h60
  text "Top Solder" at -1270.65,11306 h60
  text "Solder Resist" at -785.07,11306 h60
  text "0.40mil" at -348.72,11306 h60
  text "3.5" at 9.71,11306 h60
  text "1" at -1521.74,11186 h60
  text "Top Layer" at -1270.65,11186 h60
  text "1.40mil" at -348.72,11186 h60
  text "Dielectric 2" at -1270.65,11066 h60
  text "10.00mil" at -348.72,11066 h60
  text "4.2" at 9.71,11066 h60
  text "2" at -1521.8,10946 h60
  text "GND1" at -1270.65,10946 h60
  text "1.42mil" at -348.72,10946 h60
  text "Dielectric 3" at -1270.65,10826 h60
  text "10.00mil" at -348.72,10826 h60
  text "4.2" at 9.71,10826 h60
  text "3" at -1521.74,10706 h60
  text "Signal 1" at -1270.65,10706 h60
  text "CF-004" at -785.07,10706 h60
  text "1.38mil" at -348.72,10706 h60
  text "Dielectric 7" at -1270.65,10586 h60
  text "PP-006" at -785.07,10586 h60
  text "2.80mil" at -348.78,10586 h60
  text "4.1" at 9.71,10586 h60
  text "4" at -1521.74,10466 h60
  text "GND2" at -1270.65,10466 h60
  text "CF-004" at -785.07,10466 h60
  text "1.38mil" at -348.72,10466 h60
  text "Dielectric 9" at -1270.65,10346 h60
  text "PP-006" at -785.07,10346 h60
  text "2.80mil" at -348.78,10346 h60
  text "4.1" at 9.71,10346 h60
  text "5" at -1521.74,10226 h60
  text "Signal 2" at -1270.65,10226 h60
  text "CF-004" at -785.07,10226 h60
  text "1.38mil" at -348.72,10226 h60
  text "Dielectric 1" at -1270.65,10106 h60
  text "PP-006" at -785.07,10106 h60
  text "2.80mil" at -348.78,10106 h60
  text "4.1" at 9.71,10106 h60
  text "6" at -1521.74,9986 h60
  text "GND3" at -1270.65,9986 h60
  text "1.42mil" at -348.72,9986 h60
  text "Dielectric 11" at -1270.65,9866 h60
  text "PP-006" at -785.07,9866 h60
  text "2.80mil" at -348.78,9866 h60
  text "4.1" at 9.71,9866 h60
  text "7" at -1521.74,9746 h60
  text "Singal 3" at -1270.65,9746 h60
  text "CF-004" at -785.07,9746 h60
  text "1.38mil" at -348.72,9746 h60
  text "Dielectric1" at -1270.65,9626 h60
  text "FR-4 High Tg" at -785.07,9626 h60
  text "10.00mil" at -348.72,9626 h60
  text "4.8" at 9.71,9626 h60
  text "8" at -1521.74,9506 h60
  text "Power 1" at -1270.65,9506 h60
  text "CF-004" at -785.07,9506 h60
  text "1.38mil" at -348.72,9506 h60
  text "Dielectric 12" at -1270.65,9386 h60
  text "PP-006" at -785.07,9386 h60
  text "2.80mil" at -348.78,9386 h60
  text "4.1" at 9.71,9386 h60
  text "9" at -1521.74,9266 h60
  text "GND4" at -1270.65,9266 h60
  text "1.42mil" at -348.72,9266 h60
  text "Dielectric 6" at -1270.65,9146 h60
  text "PP-006" at -785.07,9146 h60
  text "2.80mil" at -348.78,9146 h60
  text "4.1" at 9.71,9146 h60
  text "10" at -1521.74,9026 h60
  text "Power 2" at -1270.65,9026 h60
  text "CF-004" at -785.07,9026 h60
  text "1.38mil" at -348.72,9026 h60
  text "Dielectric 10" at -1270.65,8906 h60
  text "PP-006" at -785.07,8906 h60
  text "2.80mil" at -348.78,8906 h60
  text "4.1" at 9.71,8906 h60
  text "11" at -1521.74,8786 h60
  text "GND5" at -1270.65,8786 h60
  text "CF-004" at -785.07,8786 h60
  text "1.38mil" at -348.72,8786 h60
  text "Dielectric 8" at -1270.65,8666 h60
  text "PP-006" at -785.07,8666 h60
  text "2.80mil" at -348.78,8666 h60
  text "4.1" at 9.71,8666 h60
  text "12" at -1521.74,8546 h60
  text "Power 3" at -1270.65,8546 h60
  text "CF-004" at -785.07,8546 h60
  text "1.38mil" at -348.72,8546 h60
  text "Dielectric 4" at -1270.65,8426 h60
  text "10.00mil" at -348.72,8426 h60
  text "4.2" at 9.71,8426 h60
  text "13" at -1521.74,8306 h60
  text "GND6" at -1270.65,8306 h60
  text "1.42mil" at -348.72,8306 h60
  text "Dielectric 5" at -1270.65,8186 h60
  text "10.00mil" at -348.72,8186 h60
  text "4.2" at 9.71,8186 h60
  text "14" at -1521.74,8066 h60
  text "Bottom Layer" at -1270.65,8066 h60
  text "1.40mil" at -348.72,8066 h60
  text "Bottom Solder" at -1270.65,7946 h60
  text "Solder Resist" at -785.07,7946 h60
  text "0.40mil" at -348.72,7946 h60
  text "3.5" at 9.71,7946 h60
  text "Bottom Overlay" at -1270.65,7826 h60
  text ".Layer_Name" at 577,-858.49 h60
M13 Component Bodies Top:
  text ".Layer_Name" at 577,-858.49 h60
M14 Component Bodies Bottom:
  text ".Layer_Name" at 577,-858.49 h60
M15 Courtyards Top:
  text ".Layer_Name" at 577,-858.49 h60
M16 Courtyards Bottom:
  text ".Layer_Name" at 577,-858.49 h60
